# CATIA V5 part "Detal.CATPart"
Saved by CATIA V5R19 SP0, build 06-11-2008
Part number: Part1
Bounding box of the stored display mesh (mm): x 0 to 200, y 0 to 200, z 0 to 70
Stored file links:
  E:\Podręcznik\catia\Machine\Detal\Detal.CATPart
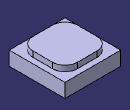
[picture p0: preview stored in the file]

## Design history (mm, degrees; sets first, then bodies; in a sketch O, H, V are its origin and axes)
Body1 "Detal" (main body)
  Sketch1 on xy-plane, origin (0, 0, 0), H (1, 0, 0), V (0, 1, 0)
    line L1 (0, 0) -> (200, 0)
    line L2 (200, 0) -> (200, 200)
    line L3 (200, 200) -> (0, 200)
    line L4 (0, 200) -> (0, 0)
    length L3 = 200
    length L2 = 200
    horizontal: L1 H, L3 H
    vertical: L2 V, L4 V
  Pad1: profile Sketch1, direction (0, 0, 1), length 50
  Sketch2 on end face of Pad1, origin (0, 0, 50), H (1, 0, 0), V (0, 1, 0)
    point P1 (20, 180)
    line L1 (65, 180) -> (135, 180)
    line L2 (180, 135) -> (180, 65)
    line L3 (135, 20) -> (65, 20)
    line L4 (20, 65) -> (20, 135)
    point P2 (180, 180)
    point P3 (180, 20)
    reference projected line E1 (0, 200) -> (0, 0) from edge [face of Pad1 from Sketch1.L4 | end face of Pad1]
    reference projected line E2 (0, 0) -> (200, 0) from edge [face of Pad1 from Sketch1.L1 | end face of Pad1]
    arc A1 centre (135, 135) radius 45 from (180, 135) to (135, 180) ccw
    arc A2 centre (65, 135) radius 45 from (65, 180) to (20, 135) ccw
    arc A3 centre (135, 65) radius 45 from (180, 65) to (135, 20) cw
    arc A4 centre (65, 65) radius 45 from (65, 20) to (20, 65) cw
    distance L4 E1 = 20
    distance L3 E2 = 20
    distance P2 P3 = 160
    distance P1 P2 = 160
    radius A1 = 45
    radius A3 = 45
    radius A4 = 45
    radius A2 = 45
    horizontal: L1 H, L3 H
    vertical: L2 V, L4 V
    coincidence: L2 P2, L1 P2, L1 P1, L4 P1, L2 P3, L3 P3
    tangency: A1 L2, A1 L1, A2 L1, A2 L4, A3 L2, A3 L3, A4 L3, A4 L4
  Pad2: profile Sketch2, direction (0, 0, 1), length 20
Body2 "Polfabrykat"
  Sketch3 on start face of Pad1, origin (0, 0, 0), H (1, 0, 0), V (0, -1, 0)
    line L1 (0, 0) -> (200, 0)
    line L2 (200, 0) -> (200, -200)
    line L3 (200, -200) -> (0, -200)
    line L4 (0, -200) -> (0, 0)
    length L1 = 200
    length L2 = 200
    horizontal: L1 H, L3 H
    vertical: L2 V, L4 V
  Pad3: profile Sketch3, direction (0, 0, 1), length 70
